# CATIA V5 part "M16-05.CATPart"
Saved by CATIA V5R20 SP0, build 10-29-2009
Part number: M16-05
Revision: ANY
Definition: UNKNOWN
Nomenclature: M16-05
Source: Unknown
Bounding box of the stored display mesh (mm): x -25 to 25, y -24.818 to 24.818, z 0 to 20
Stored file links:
  C:\Users\Utente\Desktop\IO LAVORO\3D X SITO CF\X 3D SITO CF 27-09-2020\740T\M16-05.CATPart
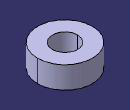
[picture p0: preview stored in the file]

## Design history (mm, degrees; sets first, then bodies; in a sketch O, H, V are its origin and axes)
Body1 "NONE" (main body)
  Solid1: solid without history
